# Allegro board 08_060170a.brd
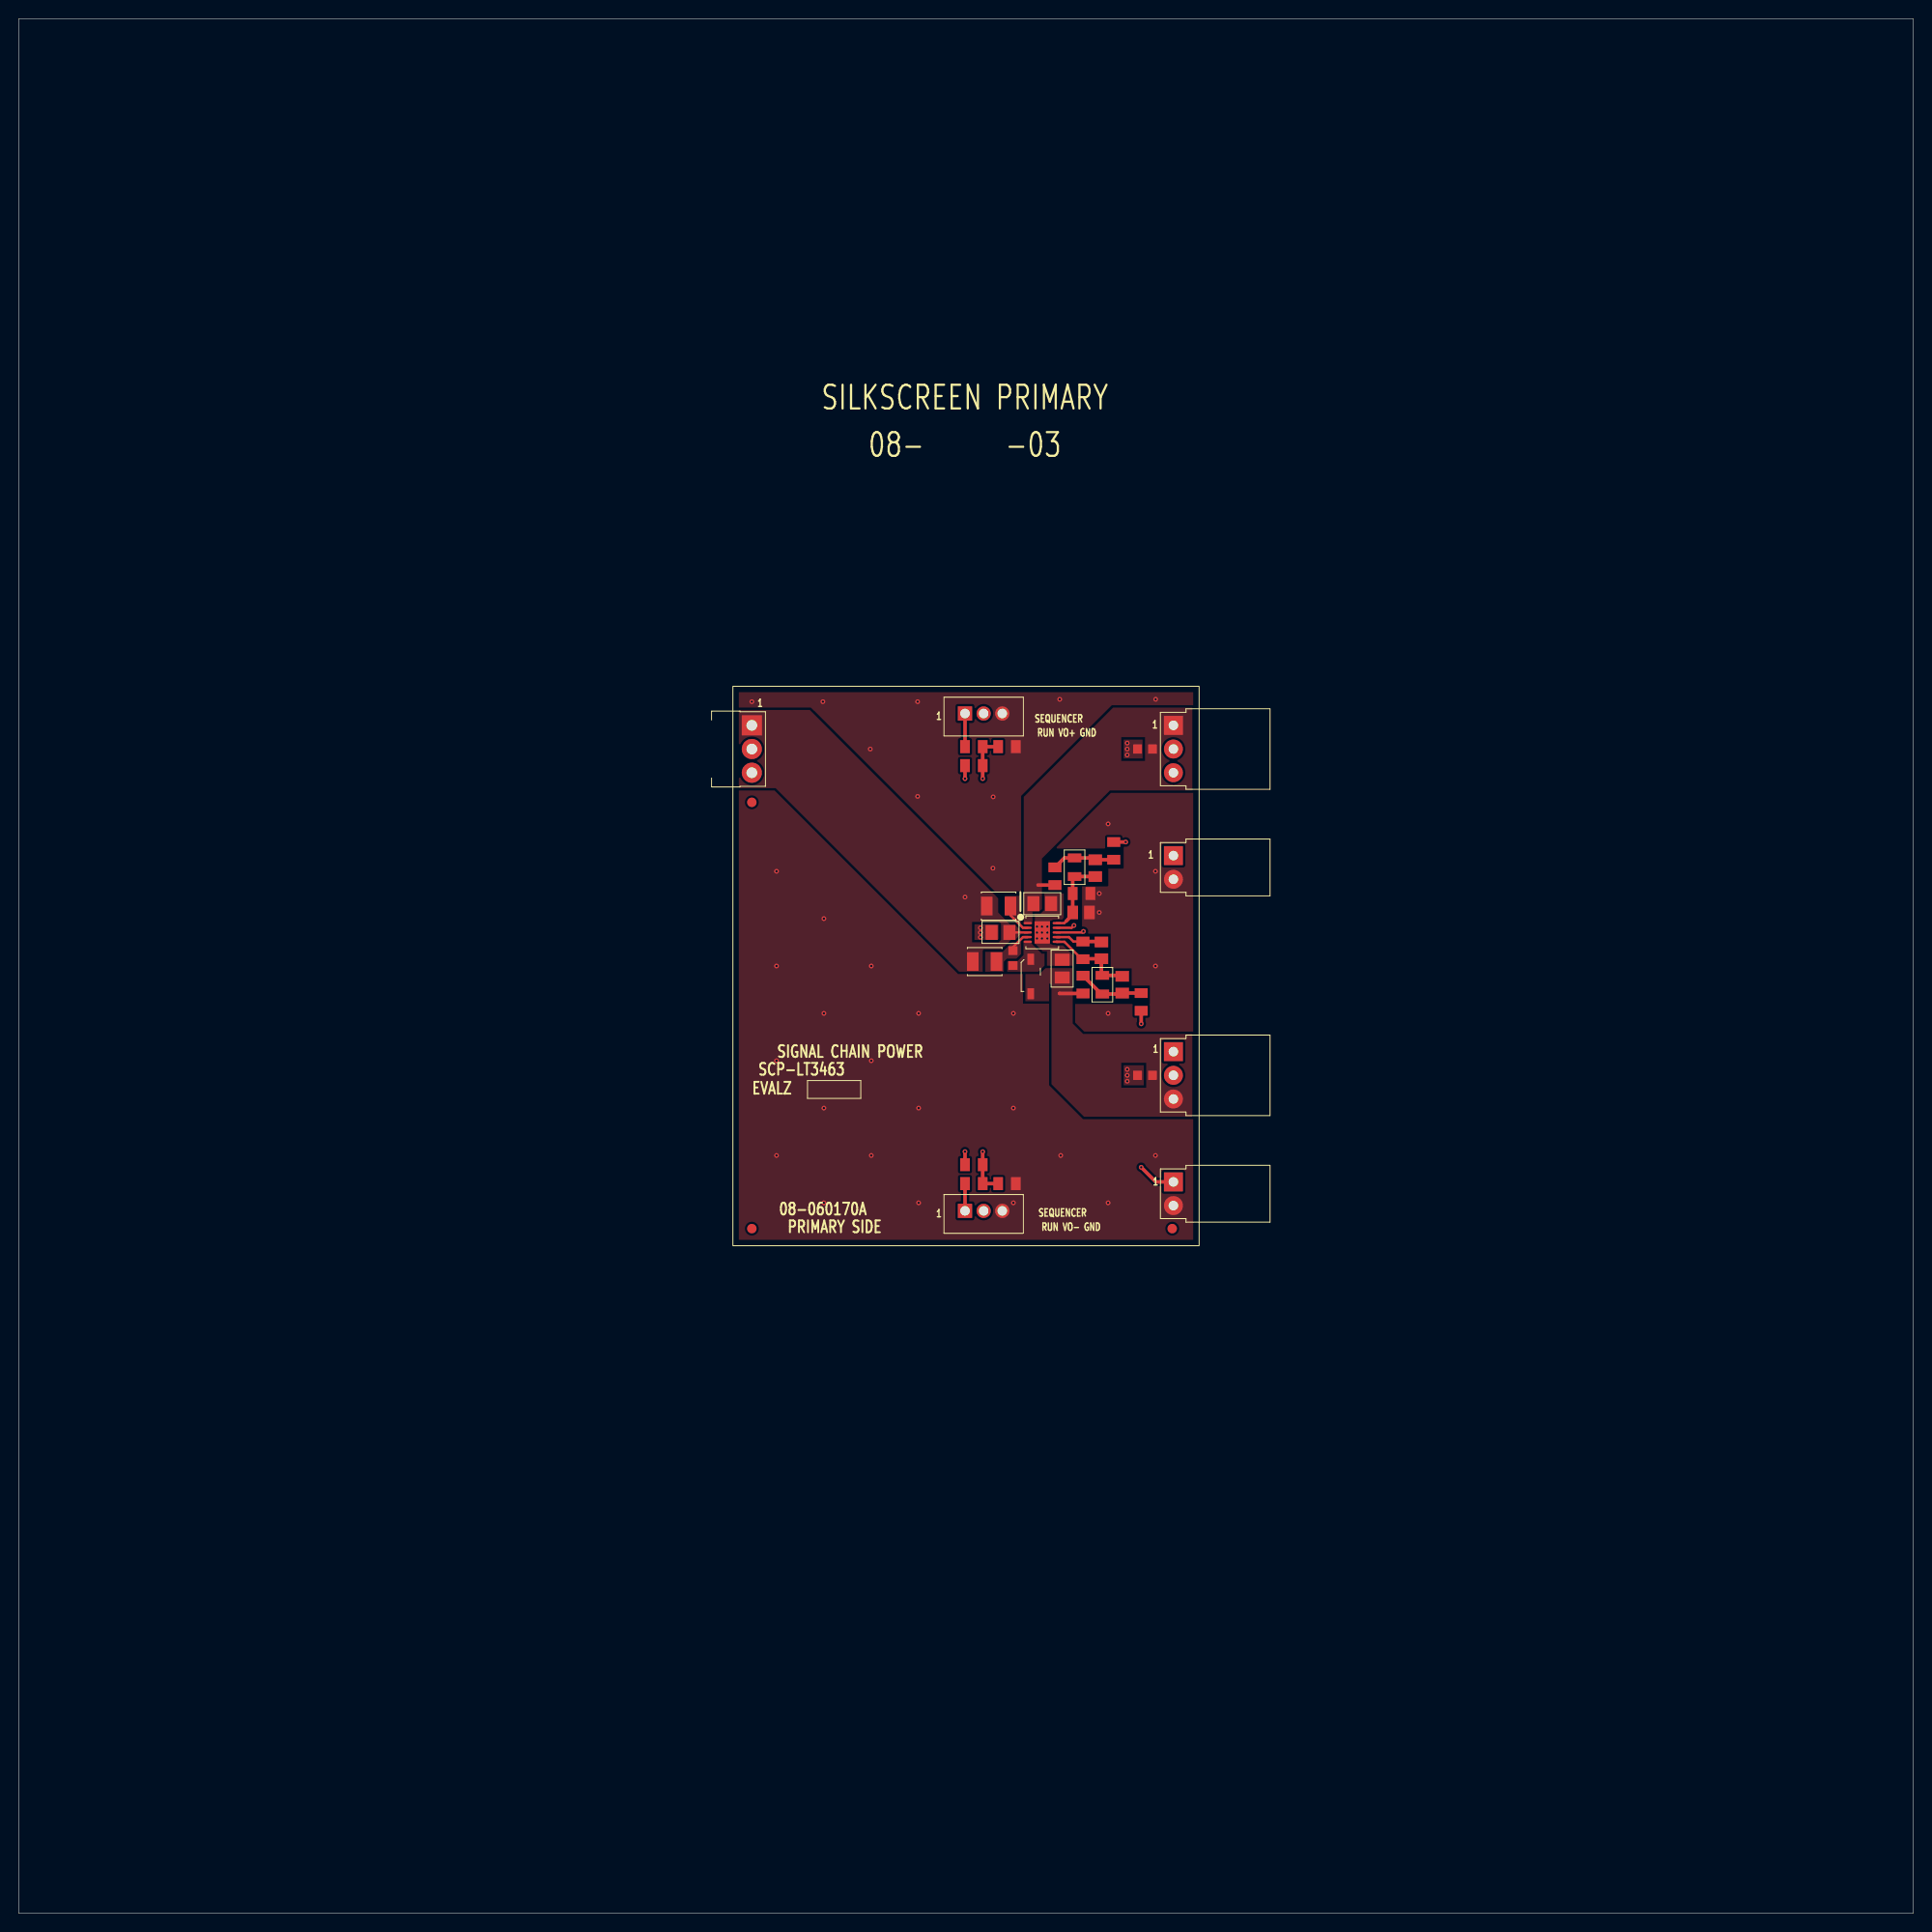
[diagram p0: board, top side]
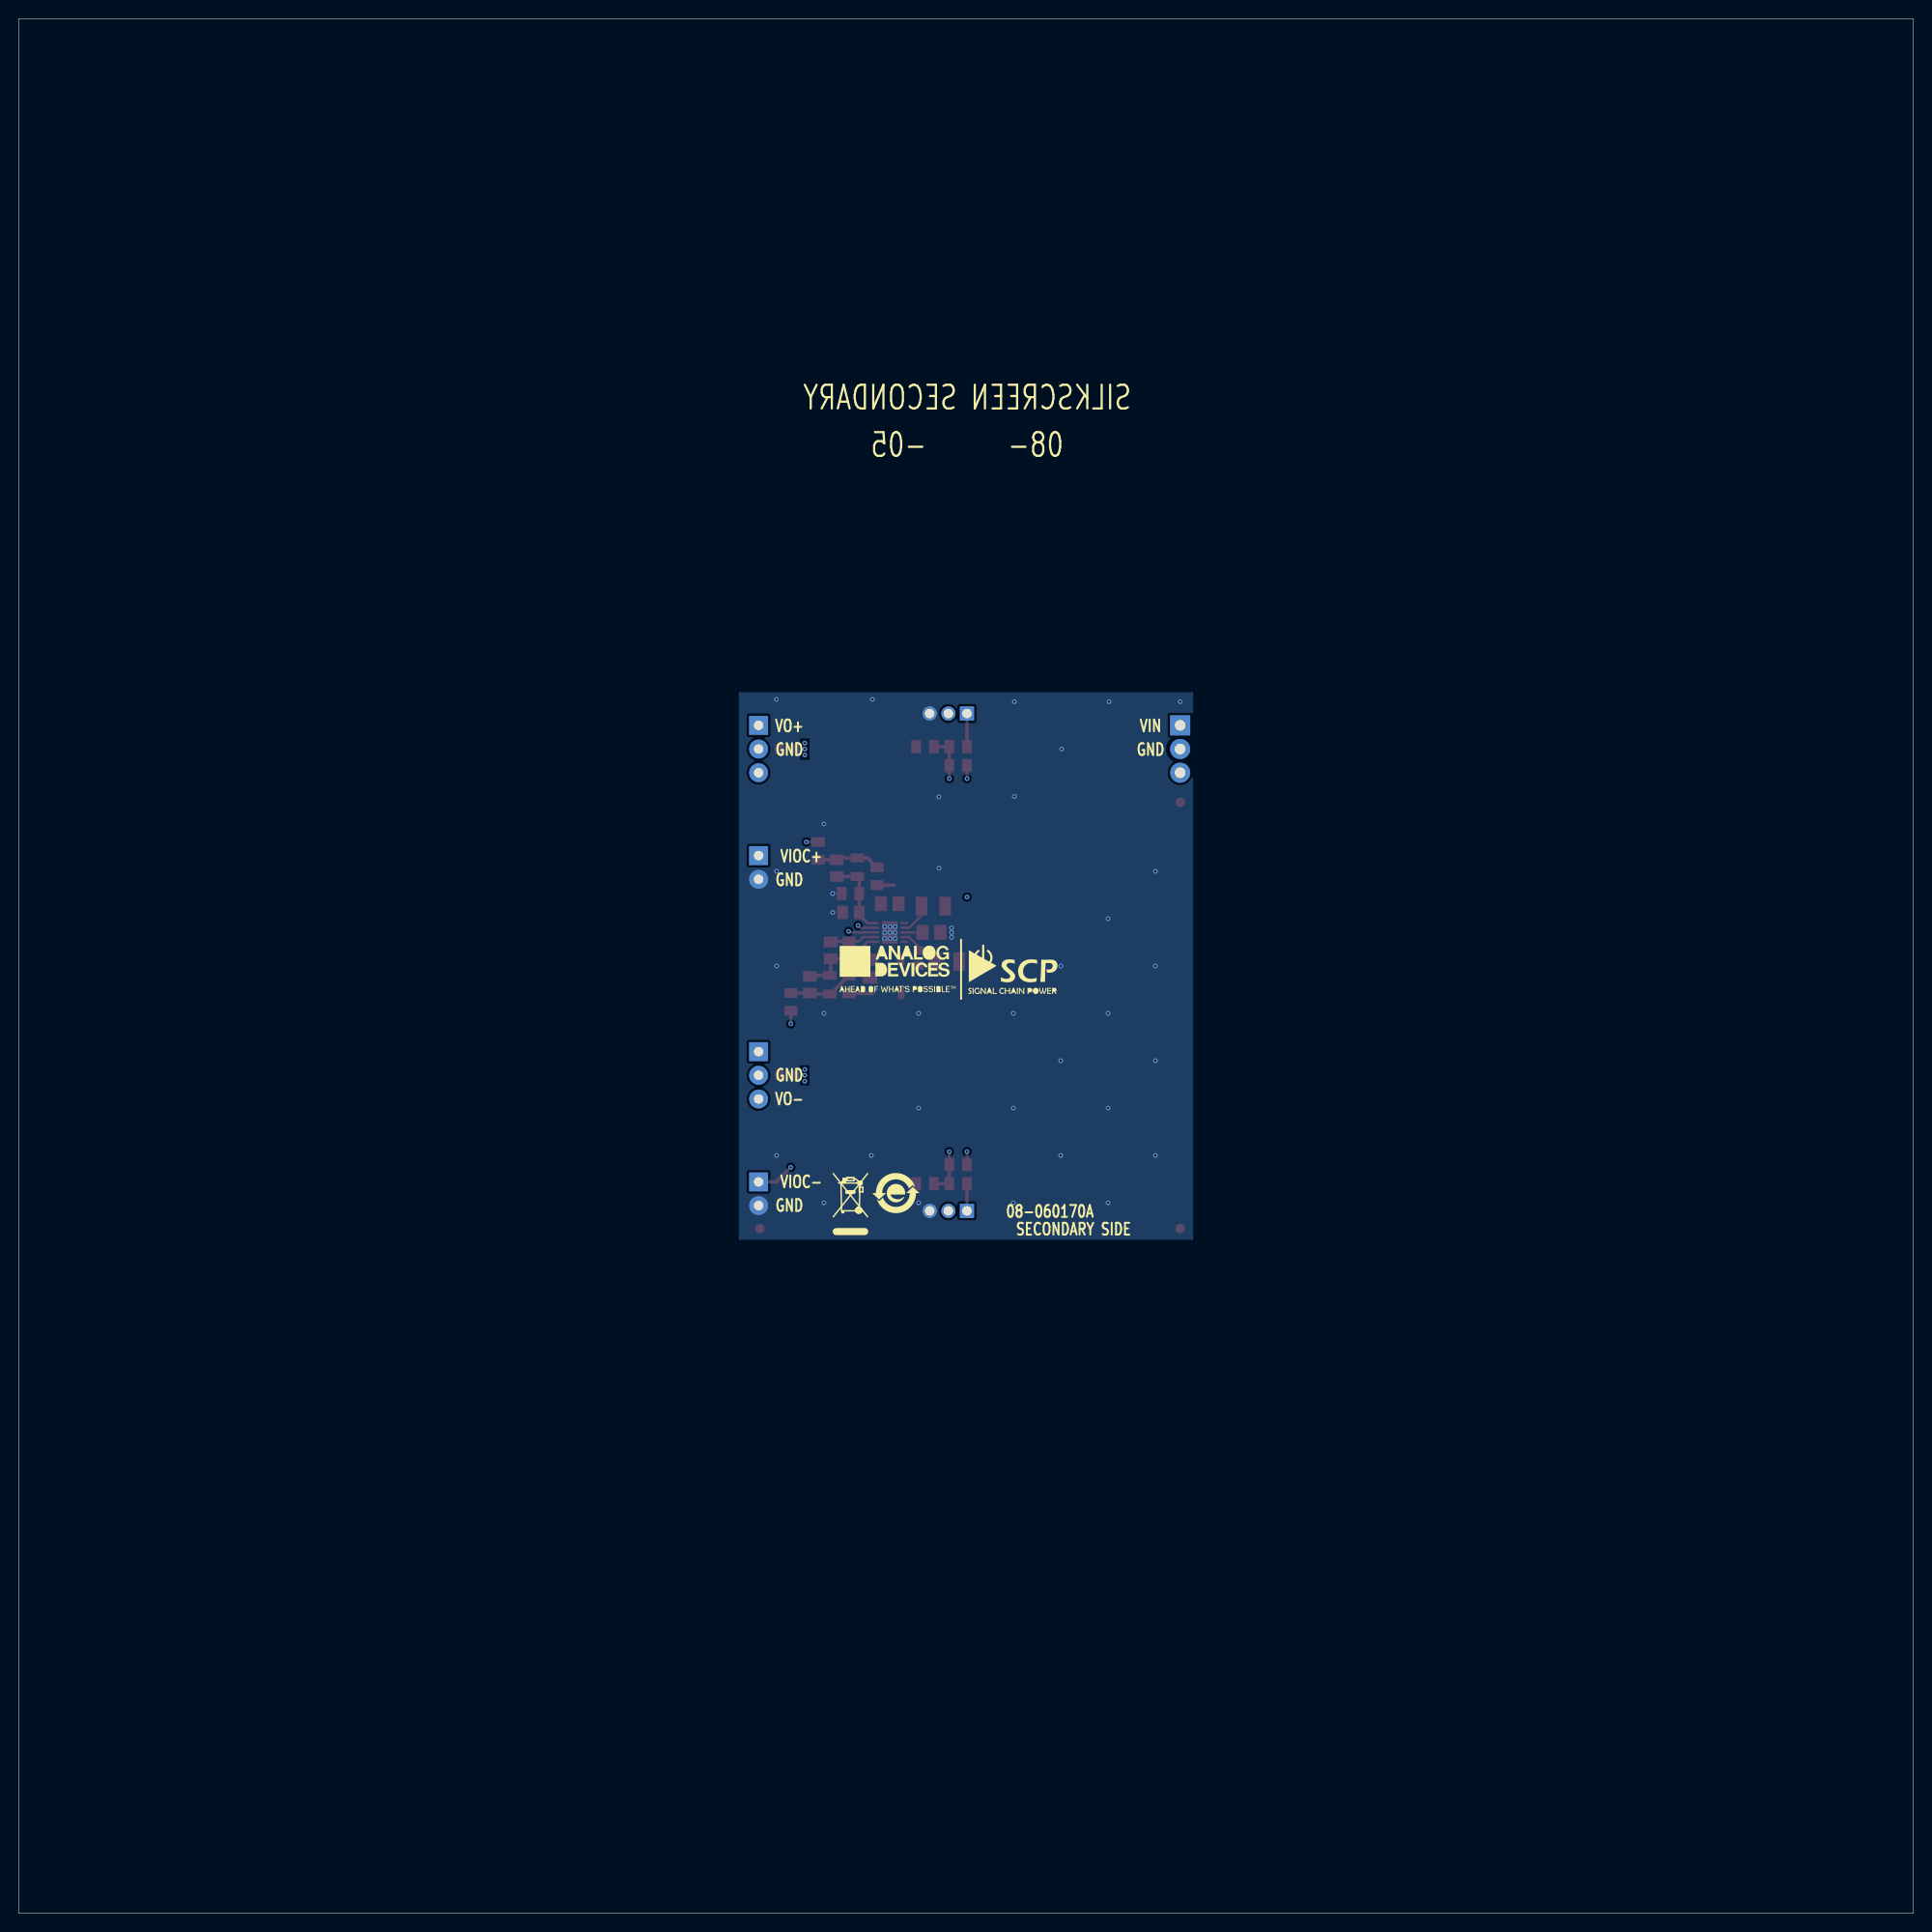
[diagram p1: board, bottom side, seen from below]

Outline 203.2 x 203.2 mm; copper layers: TOP, L2_GND, L3_SIGNAL, BOTTOM. Coordinates in mm from the lower left corner of the outline.
Outline path: 0,203.2 203.2,203.2 203.2,0 0,0 0,203.2

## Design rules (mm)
constraint set DEFAULT: min track width 0.254

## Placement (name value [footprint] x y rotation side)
C1  4.7UF  [C0805H53]  105.3 105.2 0 top
C2  1UF  [C0805H53]  109.78 108.28 180 top
C3  1UF  [C0805H53]  111.91 101.32 270 top
C4  0.1UF  [C0603]  106.63 102.46 270 top
C5  TBD0805  [C0805]  115.46 112.09 90 top
C6  TBD0805  [C0805]  113.94 107.34 0 top
C7  TBD0805  [C0805]  116.12 103.28 270 top
C8  10pF  [C0805]  118.36 99.6 270 top
C9  0.1UF  [C0603]  120.8 124.87 180 top
C10  0.1UF  [C0603]  120.8 89.88 180 top
D1  B0540W-7-F  [SOD123-3]  108.55 100.47 270 top
INPUT  PBC03SBAN  [CNTHMHDRRA1X3L300W100H145]  78.63 127.41 270 top
L1  10UH  [L1210H67]  105.1 108.03 180 top
L2  10UH  [L1210H67]  103.6 102.07 0 top
NOREF  -  []  76.6 71.6 0 top
NOREF#2  -  []  35.5 -39.29 0 top
NOREF#3  -  []  76.6 131.6 0 top
NOREF#4  -  []  78.63 127.41 0 top
NOREF#5  -  [unnamed#2]  123.72 73.43 0 top
NOREF#6  -  []  -273.05 -196.85 0 top
NOREF#7  -  []  126.6 131.6 180 top
NOREF#8  -  []  78.63 127.41 0 top
NOREF#9  -  []  126.6 71.6 90 top
NOREF#10  -  []  175.2 132.31 0 top
NOREF#11  -  []  126.6 71.6 90 top
NOREF#12  -  []  154.53 243.13 0 top
NOREF#13  -  [unnamed#2]  78.63 73.43 0 top
NOREF#14  -  []  198.62 60.99 0 top
NOREF#15  -  []  20.54 -100.96 0 top
NOREF#16  -  []  76.6 131.6 0 top
NOREF#17  -  []  76.6 131.6 0 top
NOREF#18  -  []  -273.05 -196.85 0 top
NOREF#19  -  [unnamed#2]  78.63 119.15 0 top
NOREF#20  -  []  101.47 156.34 0 top
NOREF#21  -  []  76.6 131.6 270 top
NOREF#22  -  []  114.19 72.8 180 bottom
NOREF#23  -  []  109.11 77.24 180 bottom
NOREF#24  -  []  109.24 101.25 180 bottom
NOREF#25  -  []  96.54 101.25 180 bottom
OUTPUT+  PPPC031LGBN-RC  [CNHDRRA1X3H108]  123.84 127.41 270 top
OUTPUT-  PPPC031LGBN-RC  [CNHDRRA1X3H108]  123.84 92.42 270 top
P1  53253-0370  [CNTHMHDR1X3L315W144H224]  101.49 128.68 0 top
P2  53253-0370  [CNTHMHDR1X3L315W144H224]  101.49 75.34 0 top
R1  4.53MEG  [R0805H20]  113.24 112.19 90 top
R2  301K  [R0805]  113.99 109.37 0 top
R3  280K  [R0805]  114.14 103.28 270 top
R4  4.53MEG  [R0805H20]  116.22 99.6 270 top
R5  0  [R0805]  111.14 111.23 270 top
R6  TBD0805  [R0805]  117.44 113.95 90 top
R7  0  [R0805]  114.15 99.61 90 top
R8  TBD0805  [R0805]  120.39 97.75 270 top
R9  0  [R0805]  102.44 123.09 180 top
R10  TBD0805  [R0805]  106 125.12 180 top
R11  TBD0805  [R0805]  102.44 125.12 0 top
R12  0  [R0805]  102.44 80.29 180 top
R13  TBD0805  [R0805]  106 78.26 180 top
R14  TBD0805  [R0805]  102.44 78.26 0 top
U1  LT3463AEDD#PBF  [DFN10_3X3_PAD2_38X1_64]  109.78 105.2 270 top
VIOC+  PPPC021LGBN-RC  [CNTHFHDRRA1X2L220W335H108]  123.84 113.44 270 top
VIOC-  PPPC021LGBN-RC  [CNTHFHDRRA1X2L220W335H108]  123.84 78.45 270 top

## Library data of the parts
C1 = CAP: Tolerance: 10; User Part Number: UPN; alternate symbols: (); part number: CAP_SM-4.7UF,25V,10,E034916,C0805H53; tolerance: 10
C2 C3 = CAP: Tolerance: 10; User Part Number: UPN; alternate symbols: (); part number: CAP_SM-1UF,50V,10,E033068,C0805H53; tolerance: 10
C4 = CAP: User Part Number: UPN; Tolerance: 10; alternate symbols: (C0603L); part number: CAP_SM-0.1UF,100V,10,E033337,C0603; tolerance: 10
C5-C7 = CAP: User Part Number: UPN; alternate symbols: (); part number: CAP_SM-TBD0805,TBD0805,TBD0805,E000383,C0805
C8 = CAP: User Part Number: UPN; Tolerance: 5; alternate symbols: (); part number: CAP_SM-10PF,50V,5,E012709,C0805; tolerance: 5
C9 C10 = CAP: User Part Number: UPN; Tolerance: 10; alternate symbols: (); part number: CAP_SM-0.1UF,50V,10,E038267,C0603; tolerance: 10
D1 = DIOSCHOTTKY: Tolerance: N/A; User Part Number: UPN; alternate symbols: (); part number: DIOSCHOTTKY_SM-B0540W-7-F,40V,N/A,E019694,SOD123-3; tolerance: N/A
INPUT = CN3P: Tolerance: N/A; User Part Number: UPN; alternate symbols: (CNTHMHDRRA1X3L300W100H145_SCP); part number: CN3P_TH-PBC03SBAN,E034137,CNTHMHDRRA1X3L300W100H145; tolerance: N/A
L1 L2 = IND: User Part Number: UPN; Tolerance: 10; alternate symbols: (); part number: IND_SM-10UH,10,E027590,L1210H67; tolerance: 10
OUTPUT+ OUTPUT- = CN3P: User Part Number: UPN; Tolerance: N/A; alternate symbols: (CNHDRRA1X3H108_SCP); part number: CN3P_TH-PPPC031LGBN-RC,E034111,CNHDRRA1X3H108; tolerance: N/A
P1 P2 = CN3P: Tolerance: N/A; User Part Number: UPN; alternate symbols: (); part number: CN3P_TH-53253-0370,E033940,CNTHMHDR1X3L315W144H224; tolerance: N/A
R1 R4 = RES: Tolerance: 1; User Part Number: UPN; alternate symbols: (R0805L); part number: RES_SM-4.53MEG,E040814,1/8W,1,R0805H20; tolerance: 1
R2 = RES: User Part Number: UPN; Tolerance: 0.1; alternate symbols: (R0805L); part number: RES_SM-301K,E040813,1/8W,0.1,R0805; tolerance: 0.1
R3 = RES: User Part Number: UPN; Tolerance: 0.1; alternate symbols: (R0805L); part number: RES_SM-280K,E040812,1/8W,0.1,R0805; tolerance: 0.1
R5 R7 R9 R12 = RES: User Part Number: UPN; Tolerance: N/A; alternate symbols: (R0805L); part number: RES_SM-0,E030875,1/8W,N/A,R0805; tolerance: N/A
R6 R8 R10 R11 R13 R14 = RES: User Part Number: UPN; alternate symbols: (R0805L); part number: RES_SM-TBD0805,E004051,TBD0805,TBD0805,R0805
U1 = ADLT3463: Tolerance: N/A; User Part Number: UPN; alternate symbols: (); part number: ADLT3463_SM-LT3463AEDD#PBF,E040555,DFN10_3X3_PAD2_38X1_64; tolerance: N/A
VIOC+ VIOC- = CN2P: Tolerance: N/A; User Part Number: UPN; alternate symbols: (CNTHFHDRRA1X2L220W335H108_SCP); part number: CN2P_TH-PPPC021LGBN-RC,E034113,CNTHFHDRRA1X2L220W335H108; tolerance: N/A

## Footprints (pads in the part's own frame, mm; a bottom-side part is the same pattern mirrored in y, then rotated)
C0603
  rect 0.94x0.991 smd: 1(-0.8,0) 2(0.8,0)
C0805
  rect 1.143x1.448 smd: 1(-0.9,0) 2(0.9,0)
C0805H53
  rect 1.295x1.6 smd: 1(-0.953,0) 2(0.953,0)
CNHDRRA1X3H108
  rect 2.032x2.032 hole 1.016: 1(0,0)
  round 2.032 hole 1.016: 2(2.54,0) 3(5.08,0)
CNTHFHDRRA1X2L220W335H108
  rect 2.032x2.032 hole 1.016: 1(0,0)
  round 2.032 hole 1.016: 2(2.54,0)
CNTHMHDR1X3L315W144H224
  rect 1.524x1.524 hole 1.016: 1(0,0)
  round 1.524 hole 1.016: 2(2,0) 3(4,0)
CNTHMHDRRA1X3L300W100H145
  rect 2.159x2.159 hole 1.143: 1(0,0)
  round 2.159 hole 1.143: 2(2.54,0) 3(5.08,0)
DFN10_3X3_PAD2_38X1_64
  oval 0.254x0.889 smd: 1(-1,-1.555) 2(-0.5,-1.555) 3(0,-1.555) 4(0.5,-1.555) 5(1,-1.555) 6(1,1.555) 7(0.5,1.555) 8(0,1.555) 9(-0.5,1.555) 10(-1,1.555)
  rect 2.388x1.651 smd: PAD(0,0)
L1210H67
  rect 1.245x2.007 smd: 1(-1.272,0) 2(1.272,0)
R0805
  rect 1.041x1.397 smd: 1(-0.95,0) 2(0.95,0)
R0805H20
  rect 0.94x1.448 smd: 1(-1,0) 2(1,0)
SOD123-3
  rect 1.194x0.711 smd: A(1.847,0) C(-1.847,0)
unnamed#2
  round 1.016 smd: (0,0)

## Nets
GND: C1.1 C2.1 C3.1 C6.2(N2) C9.2(N2) C10.2(N2) INPUT.2 OUTPUT+.2 OUTPUT-.2 P1.3(N3) P2.3(N3) R2.2(N2) R10.1 R13.1 U1.PAD VIOC+.2(N2) VIOC-.2(N2)
UNNAMED_2_ADLT3463_I70_D2: C4.2(N2) D1.C U1.5
UNNAMED_2_ADLT3463_I70_FB1: C5.1 C6.1 R1.1 R2.1 U1.10
UNNAMED_2_ADLT3463_I70_FB2: C7.2(N2) C8.1 R3.2(N2) R4.1 U1.6
UNNAMED_2_ADLT3463_I70_SHDN1N: R9.1 R10.2(N2) R11.2(N2) U1.9
UNNAMED_2_ADLT3463_I70_SW1: L1.1 U1.2
UNNAMED_2_ADLT3463_I70_SW2: C4.1 L2.2(N2) U1.4
UNNAMED_2_ADLT3463_I70_VIN: C1.2(N2) INPUT.1 L1.2(N2) L2.1 R9.2(N2) R12.2(N2) U1.3
UNNAMED_2_ADLT3463_I70_VREF: C7.1 R3.1 U1.7(VREF)
UNNAMED_2_CAP_I76_N2: C8.2(N2) R4.2(N2) R7.2(N2) R8.1
UNNAMED_2_CN2P_I62_N1: R6.2(N2) VIOC+.1
UNNAMED_2_CN2P_I79_N1: R8.2(N2) VIOC-.1
UNNAMED_2_CN3P_I4_N1: P1.1 R11.1
UNNAMED_2_CN3P_I52_N1: P2.1 R14.1
UNNAMED_2_RES_I43_N1: R12.1 R13.2(N2) R14.2(N2) U1.8
UNNAMED_2_RES_I65_N1: C5.2(N2) R1.2(N2) R5.1 R6.1
VO+: C2.2(N2) C9.1 OUTPUT+.1 P1.2 R5.2(N2) U1.1
VO-: C3.2(N2) C10.1 D1.A(P) OUTPUT-.3(N3) P2.2 R7.1

Pads without a net: INPUT 3; OUTPUT+ 3; OUTPUT- 1

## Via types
v1: diameter 0.508, hole 0.254, TOP to BOTTOM, 63 vias

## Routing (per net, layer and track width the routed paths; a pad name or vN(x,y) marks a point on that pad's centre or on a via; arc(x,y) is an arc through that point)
GND:
  vias: v1(78.63,129.95) v1(81.28,111.76) v1(81.28,101.6) v1(81.28,91.44) v1(81.28,81.28) v1(86.25,129.95) v1(86.36,106.68) v1(86.36,96.52) v1(86.36,86.36) v1(86.36,76.2) v1(91.33,124.87) v1(91.44,101.6) v1(91.44,91.44) v1(91.44,81.28) v1(96.41,129.95) v1(96.41,119.79) v1(96.52,96.52) v1(96.52,86.36) v1(96.52,76.2) v1(103.14,105.69) v1(103.14,105.18) v1(103.14,104.68) v1(104.51,119.74) v1(104.49,112.09) v1(106.68,96.52) v1(106.68,86.36) v1(106.68,76.2) v1(109.21,105.82) v1(109.21,105.18) v1(109.21,104.55) v1(109.75,105.82) v1(109.75,105.18) v1(109.75,104.55) v1(110.33,105.82) v1(110.33,105.18) v1(110.33,104.55) v1(111.65,130.2) v1(111.76,81.28) v1(115.89,109.37) v1(115.89,107.34) v1(116.84,116.84) v1(116.84,96.52) v1(116.84,76.2) v1(118.89,125.5) v1(118.89,124.87) v1(118.89,124.23) v1(118.89,90.51) v1(118.89,89.88) v1(118.89,89.24) v1(121.94,130.2) v1(121.92,111.76) v1(121.92,101.6) v1(121.92,81.28)
UNNAMED_2_ADLT3463_I70_FB1: length 8.5
  TOP w0.254: U1.10 112.13,106.2 112.35,106.42
  TOP w0.381: 112.35,106.42 113.04,107.11 C6.1 R2.1 113.04,110.99 R1.1 C5.1
UNNAMED_2_ADLT3463_I70_FB2: length 9.6
  TOP w0.254: U1.6 111.34,104.19 112.16,104.19 114.02,102.33 R3.2
  TOP w0.381: R3.2 114.19,102.38 C7.2 116.12,100.7 R4.1 118.26,100.6 C8.1
UNNAMED_2_ADLT3463_I70_SHDN1N: length 26.8
  TOP w0.254: U1.9 112.93,105.7 v1(113.18,105.95)
  TOP w0.381: R10.2 R11.2 R9.1 v1(103.39,121.7)
  L3_SIGNAL w0.381: v1(113.18,105.95) 103.39,115.73 v1(103.39,121.7)
UNNAMED_2_ADLT3463_I70_SW1: length 3.4
  TOP w0.254: L1.1 106.37,107.04 107.71,105.7 U1.2
UNNAMED_2_ADLT3463_I70_SW2: length 2.2
  TOP w0.254: U1.4 107.71,104.7 106.55,103.53
UNNAMED_2_ADLT3463_I70_VIN: length 44.8
  TOP w0.254: U1.3 C1.2
  TOP w0.381: v1(101.49,121.69) R9.2 ; R12.2 v1(101.49,81.69)
  L3_SIGNAL w0.381: v1(101.49,121.69) v1(101.49,108.99) v1(101.49,81.69)
UNNAMED_2_ADLT3463_I70_VREF: length 5
  TOP w0.254: U1.7 112.64,104.7 113.11,104.23 R3.1
  TOP w0.381: C7.1 116.07,104.23 R3.1
UNNAMED_2_CAP_I76_N2: length 7.1
  TOP w0.381: R7.2 116.11,98.6 R4.2 118.26,98.6 C8.2 R8.1
UNNAMED_2_CN2P_I62_N1: length 7
  TOP w0.381: R6.2 v1(118.73,114.9)
  L3_SIGNAL w0.381: VIOC+.1 122.39,114.9 v1(118.73,114.9)
UNNAMED_2_CN2P_I79_N1: length 20.9
  TOP w0.381: v1(120.39,80.01) 121.96,78.45 VIOC-.1 ; R8.2 v1(120.39,95.4)
  L3_SIGNAL w0.381: v1(120.39,95.4) v1(120.39,80.01)
UNNAMED_2_CN3P_I4_N1: length 3.6
  TOP w0.381: P1.1 R11.1
UNNAMED_2_CN3P_I52_N1: length 2.9
  TOP w0.381: R14.1 P2.1
UNNAMED_2_RES_I43_N1: length 36.1
  TOP w0.254: U1.8 114.08,105.2 v1(114.19,105.31)
  TOP w0.381: R13.2 R14.2 R12.1 v1(103.39,81.68)
  L3_SIGNAL w0.381: v1(103.39,81.68) 103.39,94.51 v1(114.19,105.31)
UNNAMED_2_RES_I65_N1: length 6.8
  TOP w0.381: R5.1 112.16,113.19 R1.2 115.26,113.19 C5.2 R6.1
VO+: length 22.7
  TOP w0.381: R5.2 109.33,110.28
  L3_SIGNAL w0.381: OUTPUT+.1 104.79,127.41 103.52,128.68 P1.2
VO-: length 31.1
  TOP w0.381: 111.63,98.66 111.64,98.66 R7.1
  L3_SIGNAL w0.381: OUTPUT-.3 123.84,81.82 118.99,76.96 105.15,76.96 103.52,75.34 P2.2

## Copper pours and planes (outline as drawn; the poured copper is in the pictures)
GND on TOP: 120.54,125.88 120.54,123.85 118.51,123.85 118.51,125.88
GND on TOP: 77.24,130.96 125.96,130.96 125.96,129.57 117.24,129.57 107.55,119.88 107.52,119.84 107.51,119.79 107.51,109.6 104.72,109.6 104.7,109.6 85.34,128.96 77.26,128.96 77.24,128.96
GND on TOP: 118.51,90.96 118.51,88.8 120.67,88.8 120.67,90.96
GND on TOP: 117.33,129.3 125.96,129.3 125.96,121.15 125.95,121.16 125.95,120.96 125.96,120.97 125.96,93.87 125.95,93.88 125.95,93.68 125.96,93.69 125.96,86.3 125.95,86.31 125.95,86.11 125.96,86.12 125.96,72.24 77.24,72.24 77.24,128.71 77.26,128.7 85.23,128.7 105.07,108.86 105.07,107.39 106.02,106.44 106.07,106.41 106.11,106.4 106.17,106.4 107.23,106.4 107.36,106.53 107.23,106.66 106.17,106.66 105.33,107.5 105.33,108.92 105.32,108.97 105.29,109.01 105.05,109.25 107.51,109.25 107.51,107.19 107.64,107.06 107.77,107.19 107.77,119.74 ; 8 cut-outs
GND on BOTTOM: 77.24,130.96 125.96,130.96 125.96,72.24 77.24,72.24 77.24,124.26 77.8,123.59 78.63,123.34 80.16,124.87 78.63,126.39 77.8,126.14 77.24,125.48 ; 4 cut-outs
GND on L2_GND: 77.24,130.96 125.96,130.96 125.96,129.57 117.24,129.57 107.55,119.88 107.52,119.84 107.51,119.79 107.51,107.19 107.64,107.06 107.77,107.19 107.77,119.71 117.37,129.31 125.96,129.31 125.96,120.42 117.04,120.42 111.76,115.14 111.76,107.11 112.01,107.11 112.01,115.03 117.14,120.17 125.96,120.17 125.96,94.57 114.27,94.57 113.3,95.54 113.3,103.23 113.05,103.23 113.05,95.44 114.16,94.32 125.96,94.32 125.96,85.43 114.26,85.43 110.76,88.93 110.76,103.28 110.51,103.28 110.51,88.82 114.15,85.18 125.96,85.18 125.96,72.24 77.24,72.24 77.24,120.42 81.07,120.42 97.73,103.76 107.23,103.76 107.36,103.89 107.23,104.02 97.83,104.02 81.17,120.68 77.24,120.68 77.24,129.06 84.86,129.06 104.67,109.25 107.36,106.56 107.36,106.94 105.05,109.25 105.05,109.25 84.98,129.31 77.24,129.31
GND on L3_SIGNAL: 77.24,130.96 125.96,130.96 125.96,72.24 77.24,72.24 ; 5 cut-outs
UNNAMED_2_ADLT3463_I70_D2 on TOP: 107.84,104.29 108.65,104.29 108.65,103.99 109.72,102.92 110.03,102.92 110.03,101.65 109.37,100.99 106.01,100.99 106.01,102.05 106.09,102.13 107.13,102.13 107.77,102.77 107.77,104.22
UNNAMED_2_ADLT3463_I70_SW1 on TOP: 105.76,109.12 107.49,109.12 107.49,105.95 107.33,105.95 105.76,107.52
UNNAMED_2_ADLT3463_I70_SW2 on TOP: 107.26,104.42 107.51,104.42 107.51,102.9 107,102.39 105.99,102.39 105.66,102.06 105.66,100.99 103.65,100.99 103.65,103.13 105.53,103.13 106.55,104.14 106.98,104.14
UNNAMED_2_ADLT3463_I70_VIN on TOP: 77.24,129.06 84.86,129.06 105.05,108.87 105.05,107.34 106.39,106 106.9,106 106.9,105.97 107.56,105.31 107.56,105.08 106.9,104.42 106.9,104.4 106.42,104.4 105.4,103.38 103.5,103.38 103.4,103.28 103.4,100.99 100.86,100.99 81.17,120.68 77.24,120.68 ; 1 cut-out
VO+ on TOP: 117.37,129.31 125.88,129.31 125.88,120.42 117.04,120.42 109.75,113.13 109.75,107.72 109.49,107.47 108.73,107.47 108.73,106.07 107.79,106.07 107.79,119.74
VO- on TOP: 110.13,101.37 113.05,101.37 113.05,95.43 114.16,94.32 125.88,94.32 125.88,85.43 114.26,85.43 110.76,88.93 110.76,99.7 110.51,99.7 110.51,97.82 107.97,97.82 107.97,100.74 109.49,100.74

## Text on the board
Ref Des/Silkscreen Bottom: VIN | GND | SECONDARY SIDE | 08-060170A | VIOC+ | VIOC- | VO+ | VO-
Ref Des/Silkscreen Top: SEQUENCER | RUN VO+ GND | RUN VO- GND | EVALZ | SCP-LT3463 | 08-060170A | PRIMARY SIDE | SIGNAL CHAIN POWER
DIMENSION: REF | DIA MAX | SEE FAB DETAIL 15
User.15: 15.    THRU VIAS TO BE FILLED WITH SOLDERMASK.
User.17: L2 GND | 08-      -07
User.18: L3 SIG | 08-      -08
User.45: FIGURE | SIZE | 10.0 | 40.0 | 45.0 | PLATED | FINISHED HOLES IN MILS | ALL UNITS ARE IN MILS | QTY | 63 | 16 | 3 | TOLERANCE/NOTES
